// Mitsubishi GX Works2 project: FX2N PLC与台达VFD-B变频器通信   PLC: FX2N/FX2NC

PROGRAM MAIN
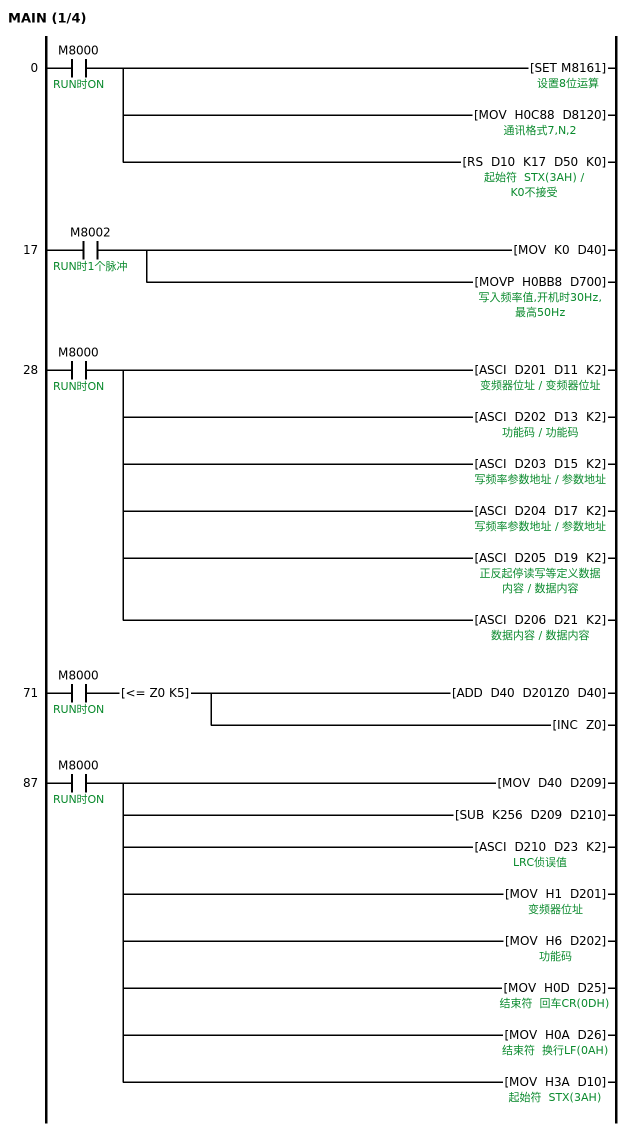
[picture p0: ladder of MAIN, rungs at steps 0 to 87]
0     LD      M8000  ; RUN时ON
      SET     M8161  ; 设置8位运算
      MOV     H0C88 D8120  ; 通讯格式7,N,2
      RS      D10 K17 D50 K0  ; 起始符  STX(3AH) / K0不接受
17    LD      M8002  ; RUN时1个脉冲
      MOV     K0 D40
      MOVP    H0BB8 D700  ; 写入频率值,开机时30Hz,最高50Hz
28    LD      M8000  ; RUN时ON
      ASCI    D201 D11 K2  ; 变频器位址 / 变频器位址
      ASCI    D202 D13 K2  ; 功能码 / 功能码
      ASCI    D203 D15 K2  ; 写频率参数地址 / 参数地址
      ASCI    D204 D17 K2  ; 写频率参数地址 / 参数地址
      ASCI    D205 D19 K2  ; 正反起停读写等定义数据内容 / 数据内容
      ASCI    D206 D21 K2  ; 数据内容 / 数据内容
71    LD      M8000  ; RUN时ON
      AND<=   Z0 K5
      ADD     D40 D201Z0 D40
      INC     Z0
87    LD      M8000  ; RUN时ON
      MOV     D40 D209
      SUB     K256 D209 D210
      ASCI    D210 D23 K2  ; LRC侦误值
      MOV     H1 D201
      MOV     H6 D202
      MOV     H0D D25  ; 结束符  回车CR(0DH)
      MOV     H0A D26  ; 结束符  换行LF(0AH)
      MOV     H3A D10
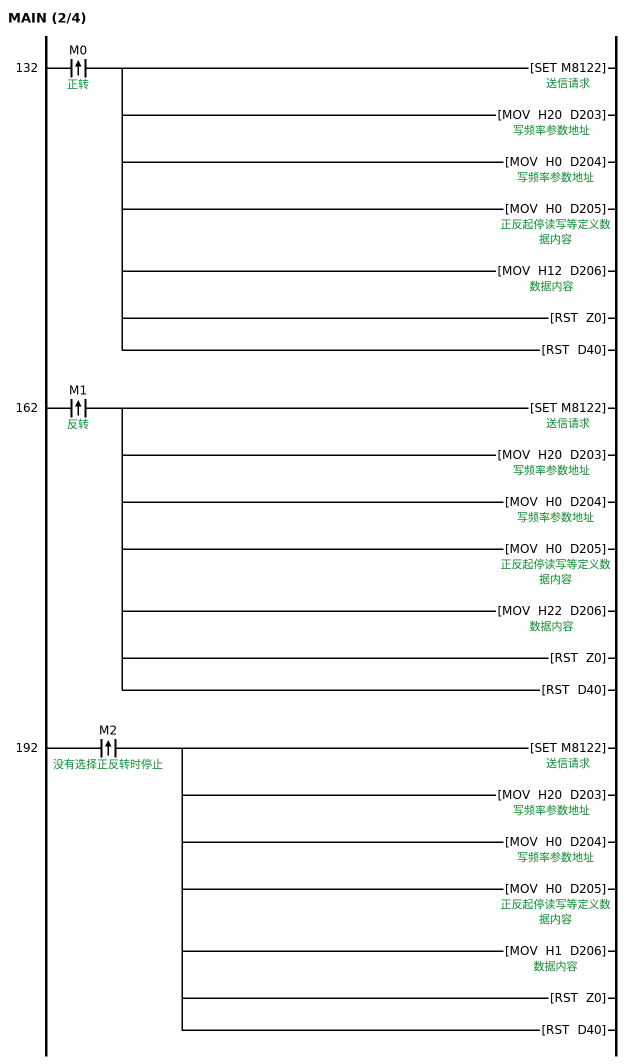
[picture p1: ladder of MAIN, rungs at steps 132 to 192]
132   LDP     M0  ; 正转
      SET     M8122  ; 送信请求
      MOV     H20 D203
      MOV     H0 D204
      MOV     H0 D205
      MOV     H12 D206
      RST     Z0
      RST     D40
162   LDP     M1  ; 反转
      SET     M8122  ; 送信请求
      MOV     H20 D203
      MOV     H0 D204
      MOV     H0 D205
      MOV     H22 D206
      RST     Z0
      RST     D40
192   LDP     M2  ; 没有选择正反转时停止
      SET     M8122  ; 送信请求
      MOV     H20 D203
      MOV     H0 D204
      MOV     H0 D205
      MOV     H1 D206
      RST     Z0
      RST     D40
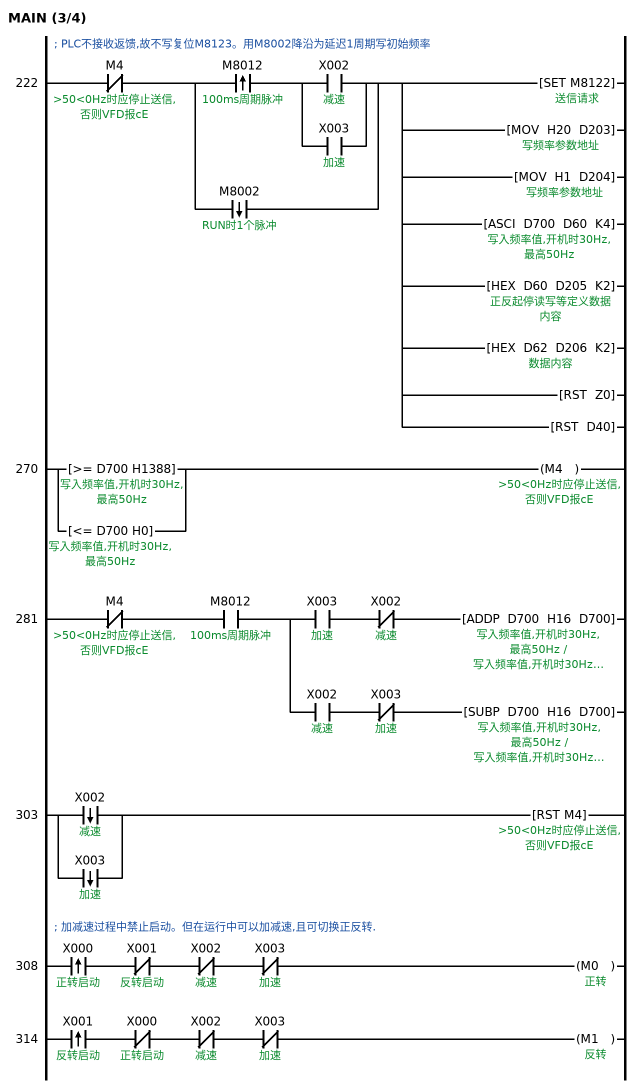
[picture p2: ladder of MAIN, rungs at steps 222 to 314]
; PLC不接收返馈,故不写复位M8123。用M8002降沿为延迟1周期写初始频率
222   LDI     M4  ; >50<0Hz时应停止送信,否则VFD报cE
      LDP     M8012  ; 100ms周期脉冲
      LD      X002  ; 减速
      OR      X003  ; 加速
      ANB
      ORF     M8002  ; RUN时1个脉冲
      ANB
      SET     M8122  ; 送信请求
      MOV     H20 D203
      MOV     H1 D204
      ASCI    D700 D60 K4
      HEX     D60 D205 K2
      HEX     D62 D206 K2
      RST     Z0
      RST     D40
270   LD>=    D700 H1388  ; 写入频率值,开机时30Hz,最高50Hz
      OR<=    D700 H0  ; 写入频率值,开机时30Hz,最高50Hz
      OUT     M4  ; >50<0Hz时应停止送信,否则VFD报cE
281   LDI     M4  ; >50<0Hz时应停止送信,否则VFD报cE
      AND     M8012  ; 100ms周期脉冲
      MPS
      AND     X003  ; 加速
      ANI     X002  ; 减速
      ADDP    D700 H16 D700
      MPP
      AND     X002  ; 减速
      ANI     X003  ; 加速
      SUBP    D700 H16 D700
303   LDF     X002  ; 减速
      ORF     X003  ; 加速
      RST     M4  ; >50<0Hz时应停止送信,否则VFD报cE
; 加减速过程中禁止启动。但在运行中可以加减速,且可切换正反转.
308   LDP     X000  ; 正转启动
      ANI     X001  ; 反转启动
      ANI     X002  ; 减速
      ANI     X003  ; 加速
      OUT     M0  ; 正转
314   LDP     X001  ; 反转启动
      ANI     X000  ; 正转启动
      ANI     X002  ; 减速
      ANI     X003  ; 加速
      OUT     M1  ; 反转
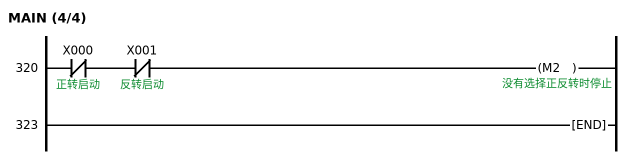
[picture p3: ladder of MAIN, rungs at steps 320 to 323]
320   LDI     X000  ; 正转启动
      ANI     X001  ; 反转启动
      OUT     M2  ; 没有选择正反转时停止
323   END
END_PROGRAM

// device comments not shown above
M8123  ; 接受完成复位
M3  ; 写入频率
